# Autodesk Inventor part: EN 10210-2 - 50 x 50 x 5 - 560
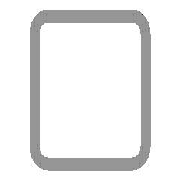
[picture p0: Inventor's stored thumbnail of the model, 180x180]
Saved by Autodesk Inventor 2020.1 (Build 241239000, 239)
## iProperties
IsCustomPart: 1
_CCFamilyMember: 16
_CCFamilyDisplayName: DIN EN 10210-2 (USAS B17.1 quadratisch) - Rohrleitung — In Klammern angegebene Größen wurden aufgehoben
_FrameMemberDoc: Frame Member File
_Version: 15.0.0
_GetPNFromCC: 1
Created: 2019-01
Part Number: EN 10210-2 - 50 x 50 x 5 - 560
Material: Stahl, weich
Description: Rohrleitung
Document SubType Name: Modeling
Standard: DIN
Designer: lutzd
Standard Revision: 2006-07
Standards Organization: DIN
Language: de-DE
Size Designation: 50 x 50 x 5
Categories: <MemberInstance><Categories><Category DisplayName="Profile" InternalName="089c4875-fa83-4c05-b084-43b9cc11f5ed" Mnemonic="GRDR"><CategoryParameter DisplayName="
Stock Number: 50 x 50 x 5
Mass: 3773.35 g
Surface Area: 1898.1 cm^2
Volume: 480.681 cm^3
Density: 7.85 g/cm^3
Appearance: Semi-Polished(8)
G_L: 560,000 mm
G_W: 50,000 mm
G_H: 50,000 mm
DocNumber: ADSK-014322
Folder: .
Dimensions: 50x50x560 mm
Mass: 3,773 kg
Title: Profil-Bauteil
Author: lutzd
Revision Number: -
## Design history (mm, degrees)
node "Startebene"
node "Endebene"
sketch "Skizze"
  geometry: L1 (-25, -17.5)-(-25, 17.5); L2 (-17.5, 25)-(17.5, 25); L3 (25, 17.5)-(25, -17.5); L4 (17.5, -25)-(-17.5, -25); L5 (-15, 20)-(15, 20); L6 (20, 15)-(20, -15); L7 (15, -20)-(-15, -20); L8 (-20, -15)-(-20, 15); L9 (0, 37.175)-(0, -37.175) reference; L10 (-37.175, 0)-(37.175, 0) reference; A1 r 7.5 centre (-17.5, -17.5) between (-25, -17.5) and (-17.5, -25); A2 r 7.5 centre (-17.5, 17.5) between (-17.5, 25) and (-25, 17.5); A3 r 7.5 centre (17.5, 17.5) between (25, 17.5) and (17.5, 25); A4 r 7.5 centre (17.5, -17.5) between (17.5, -25) and (25, -17.5); A5 r 5 centre (-15, -15) between (-20, -15) and (-15, -20); A6 r 5 centre (-15, 15) between (-15, 20) and (-20, 15); A7 r 5 centre (15, 15) between (20, 15) and (15, 20); A8 r 5 centre (15, -15) between (15, -20) and (20, -15)
  constraints: 16 end point, 16 point on circle, 16 tangent, 8 centre point, 6 equal radius, 4 parallel, 2 perpendicular, 2 other
  dimensions: "d7" = 7.5 radius of A1 (= G_IR); "d10" = 50 distance between parallel lines of L2 L4 (= G_H); "d11" = 50 distance between parallel lines of L1 L3 (= G_W); "d12" = 5 distance between parallel lines of L3 L6 (= G_T); "d15" = 25 distance between parallel lines of L2 L10 (= 0.5 x d10); "d16" = 25 distance between parallel lines of L9 L3 (= 0.5 x d11); "d19" = 5 radius of A5 (= G_T); "d20" = 5 distance between parallel lines of L4 L7 (= G_T)
extrude "Körper" new body sketch "Skizze" stored distance "d3" = 560 (= G_L); taper "d4" = 0 deg
node "Driven Length"
  sketch "Sketch3"
    geometry: L1 (0, 0)-(10, 0) reference
    constraints: 2 end point, 1 horizontal
  workplane "Work Plane3"
  sketch "Sketch4"
    geometry: L1 (-2, 0)-(12, 0) reference; L2 (-2, 560)-(12, 560) reference
    dimensions: "d18" = 560 distance between parallel lines of L1 L2 (derived)
sketch "Skizze5"
  geometry: L1 (35, 0)-(0, 0) reference; L2 (35, 560)-(0, 560) reference; 4 further points
  constraints: 2 vertical alignment, 1 midpoint
  dimensions: "d21" = 37 distance from line of point (17.5, 37) L1; "d22" = 37 distance from line of L2 point (17.5, 523) (= d21)
hole "Bohrung1" sketch "Skizze5" at (17.5, 37), (17.5, 523) diameter "d23" = 22; stored, may be unused: countersink angle "d27" = 90 deg, drill point angle "d29" = 118 deg; dims "d24" = 16, "d25" = 4, "d26" = 2, "d28" = 8
sketch "Skizze6"
  geometry: L1 (-27.75, 539.25)-(-7.25, 539.25); L2 (-7.25, 539.25)-(-7.25, 506.75); L3 (-7.25, 506.75)-(-27.75, 506.75); L4 (-27.75, 506.75)-(-27.75, 539.25); L5 (-27.75, 539.25)-(-7.25, 506.75); L6 (-7.25, 539.25)-(-27.75, 506.75); L7 (-27.75, 53.25)-(-7.25, 53.25); L8 (-7.25, 53.25)-(-7.25, 20.75); L9 (-7.25, 20.75)-(-27.75, 20.75); L10 (-27.75, 20.75)-(-27.75, 53.25); L11 (-27.75, 53.25)-(-7.25, 20.75); L12 (-7.25, 53.25)-(-27.75, 20.75); C1 r 11 at (-17.5, 523) reference; C2 r 11 at (-17.5, 37) reference; 5 further points
  constraints: 24 end point, 4 coincident, 4 midpoint, 4 parallel, 2 horizontal, 2 perpendicular
  dimensions: "d30" = 32.5 distance of L1.end L2.end; "d31" = 20.5 distance of L2.end L3.end; "d32" = 32.5 distance of L7.end L8.end (= d30); "d33" = 20.5 distance of L7.start L7.end (= d31)
hole "Bohrung2" sketch "Skizze6" at (-7.25, 539.25), (-27.75, 506.75), (-7.25, 53.25), (-27.75, 20.75) diameter "d34" = 6.647; stored, may be unused: countersink angle "d38" = 90 deg, drill point angle "d40" = 118 deg; dims "d35" = 16, "d36" = 4, "d37" = 2, "d39" = 22.2
body "Solid1"
other parameters: "G_W" = 50 [user parameter; used in 1 equation term], "G_H" = 50 [user parameter; used in 1 equation term], "G_T" = 5 [user parameter; used in 3 equation terms], "G_IR" = 7.5 [user parameter; used in 1 equation term], "G_L" = 560 (= d18) [user parameter; used in 1 equation term], "G_OFFSET_START" = 0 [user parameter; used in 1 equation term], "G_OFFSET_END" = 0 [user parameter; used in 1 equation term], "d13" = 0 (computed from G_OFFSET_START), "d17" = 90 deg
